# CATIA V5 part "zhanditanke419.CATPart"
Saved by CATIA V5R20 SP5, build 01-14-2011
Part number: 战地坦克
Material "无"
Material "Amber Mirror": density 2190 kg/m3, Young's modulus 6.5e+10 Pa, Poisson ratio 0.161, thermal expansion 8e-05 1/K
Material "Chroma": density 7190 kg/m3, Young's modulus 7e+10 Pa, Poisson ratio 0.3, thermal expansion 6.2e-06 1/K
Bounding box of the stored display mesh (mm): x -76 to 76, y -82.378 to 124.342, z -59.737 to 50.223
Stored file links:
  C:\Documents and Settings\Student\桌面\180211214 王建龙\zhanditanke419.CATPart
  C:\Program Files\Dassault Systemes\B20\intel_a\startup\materials\Catalog.CATMaterial
  C:\Program Files\Dassault Systemes\B20\intel_a\startup\materials\DS_star.jpg
  C:\Program Files\Dassault Systemes\B20\intel_a\startup\materials\eroded_metal_1.jpg
  C:\Program Files\Dassault Systemes\B20\intel_a\startup\materials\eroded_metal_2.jpg
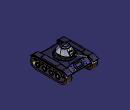
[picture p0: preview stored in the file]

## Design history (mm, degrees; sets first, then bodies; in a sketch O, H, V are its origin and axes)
Body1 (main body), material "Amber Mirror"
  Sketch1 on yz-plane, origin (0, 0, 0), H (0, 1, 0), V (0, 0, 1)
    line L1 (60, 0) -> (-55, 0)
    point P1 (60, 0)
    point P2 (-55, 0)
    line L2 (-55, 0) -> (-75.5215, -21.9066)
    point P3 (-75.5215, -21.9066)
    line L3 (-75.5215, -21.9066) -> (-47.3215, -59.5066)
    point P4 (-47.3215, -59.5066)
    line L4 (-47.3215, -59.5066) -> (52.6785, -59.5066)
    line L5 (60, 0) -> (89.4785, -22)
    point P6 (89.4785, -22)
    line L6 (89.4785, -22) -> (52.6785, -59.5066)
    reference intersected line E1 through (0, 0) direction (0, 1) from zx-plane
    length L1 = 115
    distance P3 P6 = 165
    length L4 = 100
    distance E1 P1 = 60
    distance P2 P4 = 60
    angle L2 L3 = 100
    distance P6 L1 = 22
    length L3 = 47
    horizontal: L1 H, L4 H
  Pad1: profile Sketch1, direction (1, 0, 0), length 50, mirrored extent
  Chamfer1: length 2, angle 45, on edge [start face of Pad1 | face of Pad1 from Sketch1.L5]; edge [start face of Pad1 | face of Pad1 from Sketch1.L1]; edge [start face of Pad1 | face of Pad1 from Sketch1.L6]; edge [start face of Pad1 | face of Pad1 from Sketch1.L4]; edge [start face of Pad1 | face of Pad1 from Sketch1.L3]; edge [start face of Pad1 | face of Pad1 from Sketch1.L2]
  Chamfer2: length 2, angle 45, on edge [face of Pad1 from Sketch1.L1 | end face of Pad1]; edge [face of Pad1 from Sketch1.L5 | end face of Pad1]; edge [face of Pad1 from Sketch1.L4 | end face of Pad1]; edge [face of Pad1 from Sketch1.L6 | end face of Pad1]; edge [face of Pad1 from Sketch1.L2 | end face of Pad1]; edge [face of Pad1 from Sketch1.L3 | end face of Pad1]
  Chamfer3: length 2, angle 45, on edge [face of Pad1 from Sketch1.L5 | face of Pad1 from Sketch1.L6]; edge [face of Pad1 from Sketch1.L3 | face of Pad1 from Sketch1.L2]
  Sketch2 on yz-plane, origin (0, 0, 0), H (0, 1, 0), V (0, 0, 1)
    axis line L1 (8, 31.3131) -> (8, -78.6869)
    line L2 (98, 4) -> (8, 4)
    point P4 (8, 4)
    reference projected line E1 (60, 0) -> (-55, 0) from edge [face of Pad1 from Sketch1.L1 | face of Chamfer2]
    line L3 (98, 4) -> (98, -10)
    point P6 (48.7077, 0)
    coniccurve C1
    distance V L1 = 8
    distance L2 E1 = 4
    length L3 = 14
    distance L1 L3 = 90
    vertical: L1 V, L3 V
    coincidence: P4 L1, P6 H
    horizontal: L2 H
  Groove1: profile Sketch2, axis Sketch2.L1, angle 360
  Sketch3 on face of Pad1 from Sketch1.L1, origin (0, 0, 0), H (1, 0, 0), V (0, 1, 0)
    reference projected circle E1 centre (0, 8) radius 40.7077 from edge [face of Pad1 from Sketch1.L1 | face of Groove1 from Sketch2.C1]
    circle A1 centre (0, 10) radius 25
    point P1 (0, 10)
    distance E1 V = 40.7077
    radius A1 = 25
    coincidence: P1 V
  Plane1: type Offset, RefPlane xy-plane, Offset 12
  Plane2: type Offset, RefPlane xy-plane, Offset 35
  Sketch4 on Plane2, origin (0, 0, 35), H (1, 0, 0), V (0, 1, 0)
    circle A1 centre (0, 10) radius 17.5
    point P1 (0, 10)
    radius A1 = 17.5
    coincidence: P1 V
  Sketch5 on Plane1, origin (0, 0, 12), H (1, 0, 0), V (0, 1, 0)
    point P1 (0, -27.5)
    coincidence: P1 V
  Sketch6 on Plane1, origin (0, 0, 12), H (1, 0, 0), V (0, 1, 0)
  Sketch7 on Plane1, origin (0, 0, 12), H (1, 0, 0), V (0, 1, 0)
    point P1 (0, 10)
    ellipse A1 centre (0, 10) semi-axes 37.5, 30.2372 rotation 270
    "Radius" A1 = 37.5
    coincidence: P1 V
  Loft1: solid, Sections (Sketch3; Sketch7)
  Loft2: solid, Sections (edge [face of Loft1 | face of Loft1]; Sketch4)
  Chamfer4: length 2, angle 2, on face of Groove1 from Sketch2.C1; edge [face of Loft1 | face of Loft2]
  Shell1: ExtOffset 0, Face face of Loft2, IntOffset 3, deactivated
  Shell2: ExtOffset 0, Face face of Loft2, IntOffset 1
  Sketch8 on xy-plane, origin (0, 0, 0), H (1, 0, 0), V (0, 1, 0)
    circle A1 centre (34.9062, 8.4465) radius 3.3172
    circle A2 centre (-35.2554, 6.7758) radius 3.3744
    circle A3 centre (-33.2444, 22.8147) radius 2.1671
    circle A4 centre (32.4483, 22.8147) radius 2.4579
    circle A5 centre (-31.3451, -8.2607) radius 2.3664
    circle A6 centre (31.778, -7.1469) radius 2.3972
    circle A7 centre (25.0746, 35.735) radius 1.7973
    circle A8 centre (-24.9769, 35.735) radius 1.7477
    circle A9 centre (-24.9769, -18.9533) radius 1.8422
    circle A10 centre (23.6222, -18.9533) radius 1.8303
  Pad2: profile Sketch8, direction (0, 0, 1), length 2
  Fillet1: radius 2, on edge [face of Pad2 from Sketch8.A2 | end face of Pad2]
  Fillet2: radius 2, on end face of Pad2 (x2); edge [face of Pad2 from Sketch8.A6 | end face of Pad2]; edge [face of Pad2 from Sketch8.A5 | end face of Pad2]; edge [face of Pad2 from Sketch8.A3 | end face of Pad2]
  Sketch9 on Plane2, origin (0, 0, 35), H (1, 0, 0), V (0, 1, 0)
    circle A1 centre (0, 10) radius 17.269
    point P1 (0, 10)
    coincidence: P1 V
  Pad3: profile Sketch9, direction (0, 0, 1), length 5
  Draft1: Angle 12, Neutral end face of Pad3, PullDir end face of Pad3, SupportToDraft face of Pad3 from Sketch9.A1
  Chamfer5: length 3, angle 45, on end face of Pad3
  Sketch10 on Plane2, origin (0, 0, 35), H (1, 0, 0), V (0, 1, 0)
    arc A1 centre (0, 10.6383) radius 8.4661 from (8.4661, 10.6383) to (-8.4661, 10.6383) ccw
    point P1 (0, 10.6383)
    arc A2 centre (0, 10.6383) radius 5.2962 from (5.2962, 10.6383) to (-5.2962, 10.6383) ccw
    line L1 (-8.4661, 10.6383) -> (-5.2962, 10.6383)
    point P3 (8.4661, 10.6383)
    point P5 (5.2962, 10.6383)
    line L2 (5.2962, 10.6383) -> (8.4661, 10.6383)
    coincidence: P1 V, L1 P3, L1 P5, L1 L2
    horizontal: L1 H, L2 H
  Sketch11 on face of Pad1 from Sketch1.L5, origin (0, 21.4637, 28.7599), H (-1, 0, 0), V (0, -0.8014, 0.5981)
    arc A1 centre (0, -67.3193) radius 21.5259 from (-18.0572, -55.6017) to (-18.0572, -79.0368) ccw
    point P1 (0, -67.3193)
    line L1 (-18.0572, -55.6017) -> (18.0572, -55.6017)
    line L2 (-18.0572, -79.0368) -> (18.0572, -79.0368)
    point P5 (18.0572, -79.0368)
    arc A2 centre (0, -67.3193) radius 21.5259 from (18.0572, -79.0368) to (18.0572, -55.6017) ccw
    line L3 (-13.2635, -61.5717) -> (13.2562, -61.5717)
    line L4 (13.2562, -61.5717) -> (13.2562, -72.9623)
    line L5 (13.2562, -72.9623) -> (-13.2635, -72.9623)
    line L6 (-13.2635, -72.9623) -> (-13.2635, -61.5717)
    coincidence: P1 V, P5 A1, A1 A2
    horizontal: L1 H, L2 H, L3 H, L5 H
    vertical: L4 V, L6 V
  Pad4: profile Sketch11, direction (0, 0.5981, 0.8014), length 2
  Sketch12 on face of Pad1 from Sketch1.L5, origin (0, 21.4637, 28.7599), H (-1, 0, 0), V (0, -0.8014, 0.5981)
    circle A1 centre (30.1647, -59.7938) radius 1.5
    circle A2 centre (30.1647, -68.712) radius 1.5
    circle A3 centre (30.1647, -76.8006) radius 1.5
    circle A4 centre (-29.7493, -59.7938) radius 1.5
    circle A5 centre (-29.7493, -68.712) radius 1.5
    circle A6 centre (-29.7493, -76.8006) radius 1.5
    radius A6 = 1.5
    radius A1 = 1.5
    radius A2 = 1.5
    radius A3 = 1.5
    radius A4 = 1.5
    radius A5 = 1.5
  Pad5: profile Sketch12, direction (0, 0.5981, 0.8014), length 1.5
  Fillet3: radius 1.5, on edge [face of Pad5 from Sketch12.A4 | end face of Pad5]; edge [face of Pad5 from Sketch12.A5 | end face of Pad5]; end face of Pad5; edge [face of Pad5 from Sketch12.A3 | end face of Pad5]; edge [face of Pad5 from Sketch12.A2 | end face of Pad5]; edge [face of Pad5 from Sketch12.A1 | end face of Pad5]; edge [face of Pad5 from Sketch12.A6 | end face of Pad5]
  Fillet4: radius 1, on end face of Pad4
  Sketch13 on yz-plane, origin (0, 0, 0), H (0, 1, 0), V (0, 0, 1)
    line L1 (34.3757, 25.6402) -> (46.2818, 12.3677)
    point P1 (34.3757, 25.6402)
    point P2 (46.2818, 12.3677)
    line L2 (46.2818, 12.3677) -> (38.4887, 4.4904)
    point P3 (46.2818, 12.3677)
    point P4 (38.4887, 4.4904)
    line L3 (34.3757, 25.6402) -> (40.3288, 25.6402)
    point P5 (34.3757, 25.6402)
    line L4 (40.3288, 25.6402) -> (52.2349, 12.3677)
    line L5 (52.2349, 12.3677) -> (44.4418, 4.4904)
    line L6 (38.4887, 4.4904) -> (44.4418, 4.4904)
    point P9 (38.4887, 4.4904)
    coincidence: P3 L1, P9 L2, P1 P5, P2 P3, P4 P9
    horizontal: L3 H, L6 H
    parallelism: L4 L1, L5 L2
  Shaft1: profile Sketch13, axis axis of face of Pad3 from Sketch9.A1, angle 18, second angle 18
  Fillet5: radius 2, on face of Shaft1 from Sketch13.L3; edge [face of Shaft1 from Sketch13.L4 | face of Shaft1]; edge [face of Shaft1 | face of Shaft1 from Sketch13.L4]; edge [face of Shaft1 from Sketch13.L4 | face of Shaft1 from Sketch13.L5]; edge [face of Shaft1 from Sketch13.L5 | face of Shaft1]; face of Shaft1 from Sketch13.L5; edge [face of Shaft1 | face of Shaft1 from Sketch13.L6]; edge [face of Shaft1 from Sketch13.L6 | face of Shaft1]
  Sketch14 on yz-plane, origin (0, 0, 0), H (0, 1, 0), V (0, 0, 1)
    line L1 (43.8404, 21.3771) -> (122.0924, 50.4532)
    line L2 (43.8404, 21.3771) -> (46.9486, 18.5411)
    line L3 (46.9486, 18.5411) -> (123.3954, 46.9465)
    line L4 (122.0924, 50.4532) -> (123.3954, 46.9465)
    parallelism: L3 L1
    perpendicularity: L4 L1
  Shaft2: profile Sketch14, axis Sketch14.L3, angle 360
  Chamfer6: length 1, angle 30, on face of Shaft2 from Sketch14.L4
  Set1 "已提取的几何图形 (盒体.1)"
    Extract1: ExtractElem face of Loft2
    Offset1: Offset Extract1, Length 3, TrickyFaces (face of Chamfer1; face of Chamfer4; face of Chamfer2; face of Chamfer4; face of Chamfer4)
Body2, material "Chroma"
  Plane3: type Offset, RefPlane yz-plane, Offset 50
  Sketch15 on Plane3, origin (50, 0, 0), H (0, 1, 0), V (0, 0, 1)
    construction line L1 (-56.8429, -34.0149) -> (66.8277, -34.0149)
    line L2 (-56.8429, -8.2926) -> (66.8277, -8.2926)
    line L3 (66.8277, -59.7371) -> (-56.8429, -59.7371)
    arc A1 centre (66.8277, -34.0149) radius 25.7223 from (66.8277, -8.2926) to (66.8277, -59.7371) cw
    arc A2 centre (-56.8429, -34.0149) radius 25.7223 from (-56.8429, -59.7371) to (-56.8429, -8.2926) cw
    construction line L4 (-56.8429, -34.0149) -> (66.8277, -34.0149)
    line L5 (-56.8429, -15.1345) -> (66.8277, -15.1345)
    line L6 (66.8277, -52.8952) -> (-56.8429, -52.8952)
    arc A3 centre (66.8277, -34.0149) radius 18.8803 from (66.8277, -15.1345) to (66.8277, -52.8952) cw
    arc A4 centre (-56.8429, -34.0149) radius 18.8803 from (-56.8429, -52.8952) to (-56.8429, -15.1345) cw
    distance L1 L2 = 25.7223
    distance L4 L5 = 18.8803
    horizontal: L1 H, L4 H
    tangency: A1 L2, A2 L2, A1 L3, A2 L3, A3 L5, A4 L5, A3 L6, A4 L6
  Pad6: profile Sketch15, direction (1, 0, 0), length 26
  Sketch16 on Plane3, origin (50, 0, 0), H (0, 1, 0), V (0, 0, 1)
    circle A1 centre (-52.5129, -40.7309) radius 11.1188
    circle A2 centre (-20.1386, -40.7309) radius 11.3958
    circle A3 centre (13.7897, -40.7309) radius 11.18
    circle A4 centre (45.128, -40.7309) radius 11.4932
    circle A5 centre (-64.6856, -24.7222) radius 6.5567
    circle A6 centre (-52.5129, -40.7309) radius 6.2595
    circle A7 centre (-64.6856, -24.7222) radius 3.519
    circle A8 centre (-20.1386, -40.7309) radius 6.83
    circle A9 centre (13.7897, -40.7309) radius 6.1724
    circle A10 centre (45.128, -40.7309) radius 6.7676
    circle A11 centre (-35.9373, -24.7222) radius 7.8719
    circle A12 centre (-2.268, -24.7222) radius 8.2727
    circle A13 centre (30.8833, -24.7222) radius 7.6486
    circle A14 centre (67.9195, -24.7222) radius 8.4507
    circle A15 centre (-35.9373, -24.7222) radius 4.9209
    circle A16 centre (-2.268, -24.7222) radius 4.9209
    circle A17 centre (30.8833, -24.7222) radius 4.751
    circle A18 centre (67.9195, -24.7222) radius 5.3369
  Pad7: profile Sketch16, direction (1, 0, 0), length 22
  Chamfer7: length 1, angle 45, on edge [face of Pad7 from Sketch16.A1 | end face of Pad7]; edge [end face of Pad7 | face of Pad7 from Sketch16.A7]; edge [face of Pad7 from Sketch16.A11 | end face of Pad7]; edge [end face of Pad7 | face of Pad7 from Sketch16.A15]; edge [face of Pad7 from Sketch16.A5 | end face of Pad7]; edge [end face of Pad7 | face of Pad7 from Sketch16.A6]; edge [face of Pad7 from Sketch16.A2 | end face of Pad7]; edge [end face of Pad7 | face of Pad7 from Sketch16.A8]; end face of Pad7 (x4); edge [face of Pad7 from Sketch16.A13 | end face of Pad7]; edge [end face of Pad7 | face of Pad7 from Sketch16.A17]
  Sketch17 on Plane3, origin (50, 0, 0), H (0, 1, 0), V (0, 0, 1)
    line L1 (-68.6723, -7.8734) -> (-36.5878, -6.0585)
    point P2 (-36.5878, -6.0585)
    line L2 (-36.5878, -6.0585) -> (67.6301, -6.0585)
    point P3 (-36.5878, -6.0585)
    point P4 (67.6301, -6.0585)
    spline S1 through (67.6301, -6.0585) (92.2055, -13.9985) (96.3013, -17.1745)
    line L3 (-68.6723, -7.8734) -> (-79.8223, -17.1745)
    line L4 (-79.8223, -17.1745) -> (-82.4716, -13.9985)
    point P6 (-82.4716, -13.9985)
    line L5 (-82.4716, -13.9985) -> (-71.3217, -4.6974)
    point P7 (-82.4716, -13.9985)
    line L6 (-71.3217, -4.6974) -> (-36.7753, -2.7433)
    line L7 (-36.7753, -2.7433) -> (68.7678, -2.7433)
    point P10 (68.7678, -2.7433)
    spline S2 through (68.7678, -2.7433) (93.5539, -10.5946) (97.893, -13.9985)
    line L8 (97.893, -13.9985) -> (96.3013, -17.1745)
    point P11 (97.893, -13.9985)
    point P12 (96.3013, -17.1745)
    point P13 (67.6301, -6.0585)
    point P14 (96.3013, -17.1745)
    point P15 (68.7678, -2.7433)
    point P16 (97.893, -13.9985)
    coincidence: P3 L1, P13 P4, P7 L4, P15 P10, P16 P11, L8 P14, P2 P3, P14 P12, P6 P7
    horizontal: L2 H, L7 H
    perpendicularity: L4 L3
    parallelism: L5 L3, L6 L1
  Pad8: profile Sketch17, direction (1, 0, 0), length 26
  Chamfer8: length 1, angle 45, on edge [face of Pad8 from Sketch17.L5 | end face of Pad8]; end face of Pad8; edge [face of Pad8 from Sketch17.S2 | face of Pad8 from Sketch17.L8]; edge [face of Pad8 from Sketch17.L8 | face of Pad8 from Sketch17.S1]; start face of Pad8; face of Pad8 from Sketch17.L4
  Sketch18 on zx-plane, origin (0, 0, 0), H (-1, 0, 0), V (0, 0, 1)
    line L1 (-50.0551, -0.7946) -> (-50.0551, -2.6601)
    line L2 (-69.1077, -2.6601) -> (-50.0551, -2.6601)
    line L3 (-69.1077, -2.6601) -> (-50.0551, -0.7946)
    vertical: L1 V
    horizontal: L2 H
  Pad9: profile Sketch18, direction (0, 1, 0), length 39, mirrored extent
  Mirror1: of the body so far, about yz-plane
  Shaft3: profile Sketch10, axis Sketch10.L1, angle 90
  Plane4: type Offset, RefPlane face of Shaft2 from Sketch14.L4, Offset 80
  Sketch19 on Plane4, origin (0, 48.7628, 18.1188), H (1, 0, 0), V (0, -0.3483, 0.9374)
    circle A1 centre (0, 0) radius 5.9238
  Pad10: profile Sketch19, direction (0, 0.9374, 0.3483), length 8
  Sketch20 on Plane4, origin (0, 48.7628, 18.1188), H (1, 0, 0), V (0, -0.3483, 0.9374)
    circle A1 centre (0, 0) radius 4.1136
  Pad11: profile Sketch20, direction (0, 0.9374, 0.3483), length 13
